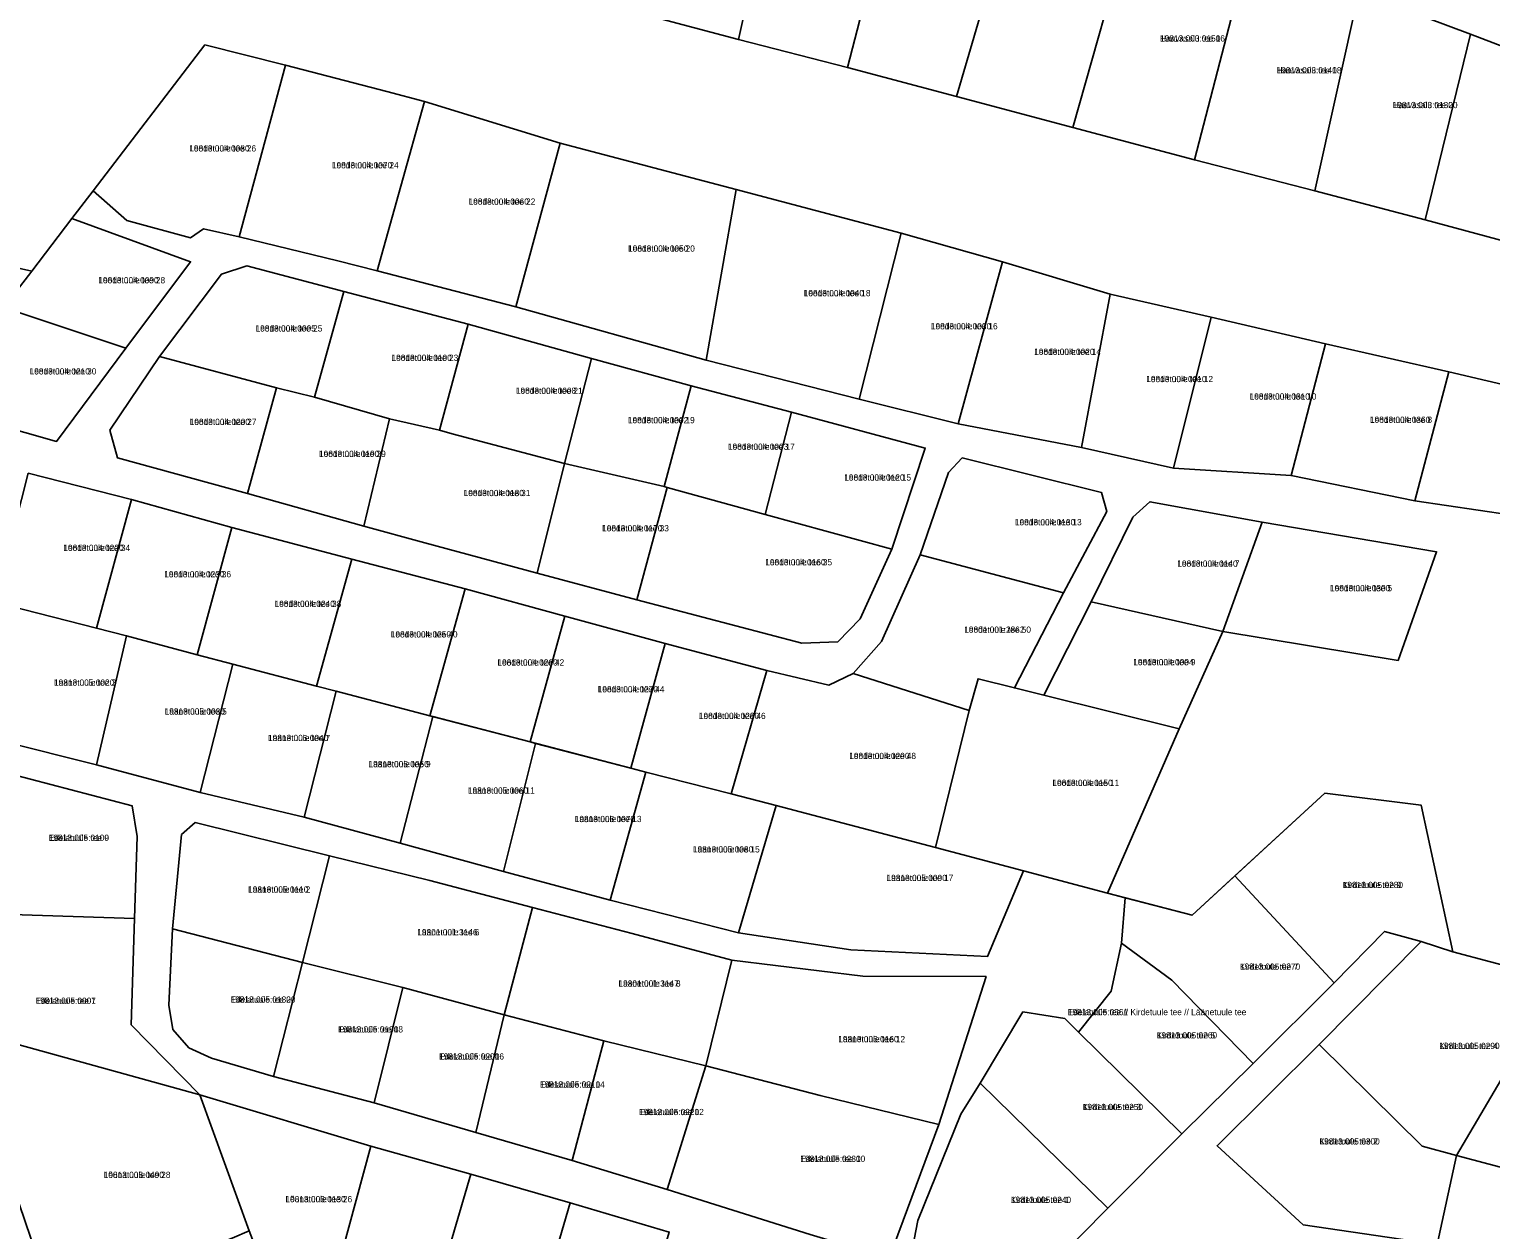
# Model space of a CAD drawing. Extents: x 516875 to 535633, y 6574491 to 6593094.
# Drawn here: x 517650.6 to 518002.1, y 6583914.7 to 6584203.6 of the extents above; entities that cross this region are included whole.
import ezdxf

# ---------------------------------------------------------------- set-up
doc = ezdxf.new("R2010")
doc.units = 0
for name, color, linetype in [('L_AADRESS', 7, 'Continuous'), ('PIIR', 7, 'Continuous'), ('TUNNUS', 7, 'Continuous')]:
    doc.layers.add(name, color=color, linetype=linetype)

msp = doc.modelspace()

# ---------------------------------------------------------------- linework, layer by layer
at = {"layer": 'PIIR'}
for points in [[(517802.26, 6584255.24), (517831.46, 6584247.67), (517821.18, 6584201.16), (517790.64, 6584209.2)], [(517831.46, 6584247.67), (517859.74, 6584242.19), (517847.33, 6584194.39), (517821.18, 6584201.16)], [(517859.74, 6584242.19), (517887.99, 6584236.68), (517873.61, 6584187.42), (517847.33, 6584194.39)], [(517887.99, 6584236.68), (517915.38, 6584228.93), (517901.53, 6584179.93), (517873.61, 6584187.42)], [(517943.51, 6584221.11), (517930.79, 6584172.17), (517901.53, 6584179.93), (517915.38, 6584228.93)], [(517943.51, 6584221.11), (517970.3, 6584212.5), (517959.76, 6584164.74), (517930.79, 6584172.17)], [(517970.3, 6584212.5), (517997.17, 6584202.41), (517986.26, 6584157.75), (517959.76, 6584164.74)], [(517997.17, 6584202.41), (518026.14, 6584191.36), (518015.68, 6584149.83), (517986.26, 6584157.75)], [(517674.1, 6584157.6), (517665.96, 6584164.7), (517692.86, 6584199.83), (517712.21, 6584194.93), (517701.1, 6584153.69), (517692.5, 6584155.6), (517689.4, 6584153.4)], [(517712.21, 6584194.93), (517736.59, 6584188.6), (517745.66, 6584186.23), (517734.23, 6584145.46), (517724.78, 6584147.89), (517701.1, 6584153.69)], [(517745.66, 6584186.23), (517778.25, 6584176.21), (517767.64, 6584136.85), (517734.23, 6584145.46)], [(517778.25, 6584176.21), (517820.61, 6584165.03), (517813.39, 6584123.96), (517767.64, 6584136.85)], [(517820.61, 6584165.03), (517860.28, 6584154.5), (517850.21, 6584114.59), (517813.39, 6584123.96)], [(517594.89, 6584064.17), (517581.91, 6584058.31), (517564.54, 6584099.9), (517607.05, 6584155.33), (517651.21, 6584145.42), (517644.46, 6584136.64), (517626.64, 6584113.1), (517620.18, 6584104.83), (517599.06, 6584076.92)], [(517660.88, 6584158.06), (517689.39, 6584147.67), (517673.82, 6584126.88), (517644.46, 6584136.64), (517651.21, 6584145.42)], [(517860.28, 6584154.5), (517884.62, 6584147.65), (517874, 6584108.63), (517850.21, 6584114.59)], [(517702.9, 6584146.7), (517696.8, 6584144.7), (517681.93, 6584124.89), (517669.95, 6584107.17), (517671.84, 6584100.48), (517703.12, 6584091.88), (517731.02, 6584084.05), (517745.73, 6584080.04), (517772.71, 6584072.69), (517796.71, 6584066.29), (517836.42, 6584055.86), (517845.01, 6584056.22), (517850.43, 6584061.73), (517858.02, 6584078.53), (517866.07, 6584102.81), (517833.94, 6584111.47), (517809.8, 6584117.8), (517785.8, 6584124.4), (517756.11, 6584132.62), (517726.29, 6584140.47)], [(517726.29, 6584140.47), (517719.23, 6584115.04), (517710.02, 6584117.33), (517681.93, 6584124.89), (517696.8, 6584144.7), (517702.9, 6584146.7)], [(517884.62, 6584147.65), (517910.52, 6584139.88), (517903.63, 6584102.98), (517874, 6584108.63)], [(517719.23, 6584115.04), (517726.29, 6584140.47), (517756.11, 6584132.62), (517749.28, 6584107.14), (517737.27, 6584109.84)], [(517910.52, 6584139.88), (517934.79, 6584134.3), (517925.77, 6584098.03), (517903.63, 6584102.98)], [(517644.46, 6584136.64), (517673.82, 6584126.88), (517657.18, 6584104.43), (517626.64, 6584113.1)], [(517934.79, 6584134.3), (517962.35, 6584127.9), (517954.04, 6584096.21), (517925.77, 6584098.03)], [(517756.11, 6584132.62), (517785.8, 6584124.4), (517779.33, 6584099.13), (517752.28, 6584106.28), (517749.28, 6584107.14)], [(517962.35, 6584127.9), (517991.96, 6584121.14), (517983.8, 6584090.13), (517954.04, 6584096.21)], [(517710.02, 6584117.33), (517703.12, 6584091.88), (517671.84, 6584100.48), (517669.95, 6584107.17), (517681.93, 6584124.89)], [(517785.8, 6584124.4), (517809.8, 6584117.8), (517803.3, 6584093.6), (517779.33, 6584099.13)], [(517991.96, 6584121.14), (518018.27, 6584114.96), (518024.6, 6584113.47), (518019.18, 6584084.93), (518014.23, 6584085.66), (517983.8, 6584090.13)], [(517710.02, 6584117.33), (517719.23, 6584115.04), (517737.27, 6584109.84), (517731.02, 6584084.05), (517703.12, 6584091.88)], [(517833.94, 6584111.47), (517827.6, 6584086.85), (517804.01, 6584093.35), (517803.3, 6584093.6), (517809.8, 6584117.8)], [(517731.02, 6584084.05), (517737.27, 6584109.84), (517749.28, 6584107.14), (517752.28, 6584106.28), (517779.33, 6584099.13), (517772.71, 6584072.69), (517745.73, 6584080.04)], [(517833.94, 6584111.47), (517866.07, 6584102.81), (517858.02, 6584078.53), (517827.6, 6584086.85)], [(517779.33, 6584099.13), (517803.3, 6584093.6), (517804.01, 6584093.35), (517796.71, 6584066.29), (517772.71, 6584072.69)], [(517871.67, 6584096.93), (517874.93, 6584100.45), (517908.46, 6584092.12), (517909.7, 6584087.6), (517899.32, 6584068.02), (517864.88, 6584077.12)], [(517650.35, 6584096.77), (517675.23, 6584090.42), (517666.8, 6584059.53), (517645.75, 6584064.86), (517642.38, 6584065.75)], [(517804.01, 6584093.35), (517827.6, 6584086.85), (517858.02, 6584078.53), (517850.43, 6584061.73), (517845.01, 6584056.22), (517836.42, 6584055.86), (517796.71, 6584066.29)], [(517675.23, 6584090.42), (517699.35, 6584083.75), (517690.98, 6584053.09), (517673.97, 6584057.62), (517666.8, 6584059.53)], [(517916, 6584086.2), (517920.1, 6584089.9), (517947.08, 6584085.04), (517937.6, 6584058.66), (517906, 6584065.85)], [(517947.08, 6584085.04), (517989.04, 6584077.89), (517979.78, 6584051.73), (517937.6, 6584058.66)], [(517699.35, 6584083.75), (517728.2, 6584076.11), (517719.66, 6584045.52), (517699.58, 6584050.82), (517690.98, 6584053.09)], [(517728.2, 6584076.11), (517755.42, 6584068.93), (517746.97, 6584038.42), (517724.37, 6584044.3), (517719.66, 6584045.52)], [(517855.58, 6584056.29), (517864.88, 6584077.12), (517899.32, 6584068.02), (517887.5, 6584045.13), (517878.76, 6584047.33), (517876.62, 6584039.66), (517848.7, 6584048.62)], [(517755.42, 6584068.93), (517779.39, 6584062.4), (517771.09, 6584032.11), (517746.97, 6584038.42)], [(517646.35, 6584044.51), (517639.15, 6584046.56), (517645.75, 6584064.86), (517666.8, 6584059.53), (517673.97, 6584057.62), (517666.74, 6584026.6), (517644.05, 6584032.34)], [(517937.6, 6584058.66), (517927.09, 6584035.31), (517894.56, 6584043.4), (517906, 6584065.85)], [(517779.39, 6584062.4), (517803.5, 6584055.8), (517795.24, 6584025.79), (517771.09, 6584032.11)], [(517690.98, 6584053.09), (517699.58, 6584050.82), (517691.68, 6584019.98), (517666.74, 6584026.6), (517673.97, 6584057.62)], [(517803.5, 6584055.8), (517828, 6584049.3), (517819.37, 6584019.64), (517798.91, 6584024.85), (517795.24, 6584025.79)], [(517719.66, 6584045.52), (517724.37, 6584044.3), (517716.68, 6584014), (517691.68, 6584019.98), (517699.58, 6584050.82)], [(517828, 6584049.3), (517842.85, 6584045.8), (517848.7, 6584048.62), (517876.62, 6584039.66), (517868.54, 6584006.7), (517830.21, 6584016.79), (517819.37, 6584019.64)], [(517876.62, 6584039.66), (517878.76, 6584047.33), (517887.5, 6584045.13), (517894.56, 6584043.4), (517927.09, 6584035.31), (517909.87, 6583995.74), (517889.7, 6584001.09), (517868.54, 6584006.7)], [(517724.37, 6584044.3), (517746.97, 6584038.42), (517747.69, 6584038.23), (517739.83, 6584007.76), (517716.68, 6584014)], [(517772.35, 6584031.78), (517764.66, 6584000.98), (517739.83, 6584007.76), (517747.69, 6584038.23), (517771.09, 6584032.11)], [(517798.91, 6584024.86), (517790.33, 6583994.05), (517764.66, 6584000.98), (517772.35, 6584031.78), (517795.24, 6584025.79)], [(517675.35, 6584016.77), (517676.59, 6584009.38), (517675.92, 6583989.6), (517631.57, 6583991.05), (517635.38, 6584018.08), (517636.16, 6584027.04)], [(517819.37, 6584019.64), (517830.21, 6584016.79), (517821.14, 6583986.2), (517790.33, 6583994.05), (517798.91, 6584024.86)], [(517940.54, 6583999.91), (517962.17, 6584019.81), (517985.32, 6584016.88), (517992.97, 6583981.64), (517985.35, 6583984.1), (517976.51, 6583986.53), (517964.39, 6583974.12)], [(517868.54, 6584006.7), (517889.7, 6584001.09), (517881.04, 6583980.51), (517848.16, 6583982.1), (517821.14, 6583986.2), (517830.21, 6584016.79)], [(517722.77, 6584004.72), (517690.53, 6584012.7), (517687.24, 6584009.84), (517685.07, 6583987.19), (517684.13, 6583968.81), (517685.13, 6583962.94), (517689.01, 6583958.54), (517694.4, 6583956), (517709.32, 6583951.59), (517733.53, 6583945.3), (517758, 6583938.17), (517781.12, 6583931.43), (517803.99, 6583924.42), (517838.37, 6583913.57), (517857.4, 6583907.94), (517869.33, 6583940.11), (517880.7, 6583975.65), (517851.04, 6583975.74), (517819.59, 6583979.63), (517795.57, 6583986.06), (517771.63, 6583992.28), (517746.94, 6583998.75)], [(517687.24, 6584009.84), (517690.53, 6584012.7), (517722.77, 6584004.72), (517716.33, 6583979.03), (517685.07, 6583987.19)], [(517740.41, 6583973), (517716.33, 6583979.03), (517722.77, 6584004.72), (517746.94, 6583998.75), (517771.63, 6583992.28), (517764.77, 6583966.45)], [(517913.22, 6583983.71), (517914.17, 6583994.61), (517930.21, 6583990.41), (517940.54, 6583999.91), (517964.39, 6583974.12), (517944.91, 6583954.71), (517925.39, 6583974.84)], [(517675.92, 6583989.6), (517675.15, 6583964.07), (517691.62, 6583947.17), (517639.15, 6583961.76), (517633.5, 6583964.01), (517628.61, 6583965.96), (517630.91, 6583986.34), (517631.57, 6583991.05)], [(517788.79, 6583960.23), (517764.77, 6583966.45), (517771.63, 6583992.28), (517795.57, 6583986.06), (517819.59, 6583979.63), (517813.27, 6583954.21)], [(517689.01, 6583958.54), (517685.13, 6583962.94), (517684.13, 6583968.81), (517685.07, 6583987.19), (517716.33, 6583979.03), (517709.32, 6583951.59), (517694.4, 6583956)], [(517910.77, 6583972.17), (517913.22, 6583983.71), (517925.39, 6583974.84), (517944.91, 6583954.71), (517927.79, 6583937.85), (517902.91, 6583962.3)], [(517960.79, 6583959.34), (517985.35, 6583984.1), (517992.97, 6583981.64), (518011.08, 6583976.77), (518018.58, 6583974.75), (517993.78, 6583932.65), (517985.59, 6583934.85)], [(517740.41, 6583973), (517733.53, 6583945.3), (517709.32, 6583951.59), (517716.33, 6583979.03)], [(517813.27, 6583954.21), (517819.59, 6583979.63), (517851.04, 6583975.74), (517880.7, 6583975.65), (517869.33, 6583940.11), (517840.79, 6583947.04)], [(517740.41, 6583973), (517764.77, 6583966.45), (517758, 6583938.17), (517733.53, 6583945.3)], [(518012.22, 6583927.69), (517993.78, 6583932.65), (518018.58, 6583974.75), (518032.77, 6583970.93), (518046.75, 6583967.18), (518032.08, 6583899), (518003.93, 6583906.25)], [(517764.77, 6583966.45), (517788.79, 6583960.23), (517781.12, 6583931.43), (517758, 6583938.17)], [(517889.55, 6583967.18), (517899.65, 6583965.54), (517902.91, 6583962.3), (517927.79, 6583937.85), (517909.96, 6583919.91), (517879.24, 6583950.04)], [(517639.15, 6583961.76), (517691.62, 6583947.17), (517703.49, 6583914.48), (517699.43, 6583912.76), (517656.57, 6583896.21), (517639.72, 6583945.75), (517633.5, 6583964.01)], [(517813.27, 6583954.21), (517803.99, 6583924.42), (517781.12, 6583931.43), (517788.79, 6583960.23)], [(517936.25, 6583934.96), (517960.79, 6583959.34), (517985.59, 6583934.85), (517993.78, 6583932.65), (517989.16, 6583911.17), (517956.97, 6583915.91)], [(517813.27, 6583954.21), (517840.79, 6583947.04), (517869.33, 6583940.11), (517857.4, 6583907.94), (517838.37, 6583913.57), (517803.99, 6583924.42)], [(517863.33, 6583903.37), (517863.38, 6583912.42), (517864.32, 6583916.96), (517874.64, 6583942.55), (517879.24, 6583950.04), (517909.96, 6583919.91), (517890.91, 6583900.6), (517883.11, 6583898.78)], [(517703.49, 6583914.48), (517691.62, 6583947.17), (517732.77, 6583934.82), (517722.39, 6583896.74), (517707.48, 6583904.06)], [(517732.77, 6583934.82), (517756.81, 6583928.1), (517745.67, 6583890.09), (517722.39, 6583896.74)], [(517756.81, 6583928.1), (517780.68, 6583921.26), (517769.63, 6583883.34), (517745.67, 6583890.09)], [(517780.68, 6583921.26), (517804.49, 6583914.18), (517793.44, 6583876.69), (517769.63, 6583883.34)]]:
    msp.add_lwpolyline(points, close=True, dxfattribs=at)
for points in [[(518018.27, 6584114.96), (517991.96, 6584121.14), (517962.35, 6584127.9), (517934.79, 6584134.3), (517910.52, 6584139.88), (517884.62, 6584147.65), (517860.28, 6584154.5), (517820.61, 6584165.03), (517778.25, 6584176.21), (517745.66, 6584186.23), (517736.59, 6584188.6), (517712.21, 6584194.93), (517692.86, 6584199.83), (517665.96, 6584164.7), (517660.88, 6584158.06), (517651.21, 6584145.42), (517607.05, 6584155.33), (517543.49, 6584169.71), (517513.07, 6584245.83)], [(517997.94, 6584210.98), (518025.49, 6584201.06), (518053.46, 6584190.76), (518106.5, 6584188), (518106.98, 6584179.93), (518078.33, 6584179.94), (518055.07, 6584180.27), (518026.14, 6584191.36), (517997.17, 6584202.41), (517970.3, 6584212.5)], [(517790.64, 6584209.2), (517821.18, 6584201.16), (517847.33, 6584194.39), (517873.61, 6584187.42), (517901.53, 6584179.93), (517930.79, 6584172.17), (517959.76, 6584164.74), (517986.26, 6584157.75), (518015.68, 6584149.83)], [(517626.64, 6584113.1), (517657.18, 6584104.43), (517673.82, 6584126.88), (517689.39, 6584147.67), (517660.88, 6584158.06), (517665.96, 6584164.7), (517674.1, 6584157.6), (517689.4, 6584153.4), (517692.5, 6584155.6), (517701.1, 6584153.69), (517724.78, 6584147.89), (517734.23, 6584145.46), (517767.64, 6584136.85), (517813.39, 6584123.96), (517850.21, 6584114.59), (517874, 6584108.63), (517903.63, 6584102.98), (517925.77, 6584098.03), (517954.04, 6584096.21), (517983.8, 6584090.13), (518014.23, 6584085.66)], [(518011.08, 6583976.77), (517992.97, 6583981.64), (517985.32, 6584016.88), (517962.17, 6584019.81), (517930.21, 6583990.41), (517909.87, 6583995.74), (517927.09, 6584035.31), (517937.6, 6584058.66), (517979.78, 6584051.73), (517989.04, 6584077.89), (517947.08, 6584085.04), (517920.1, 6584089.9), (517916, 6584086.2), (517906, 6584065.85), (517894.56, 6584043.4), (517887.5, 6584045.13), (517899.32, 6584068.02), (517909.7, 6584087.6), (517908.46, 6584092.12), (517874.93, 6584100.45), (517871.67, 6584096.93), (517864.88, 6584077.12), (517855.58, 6584056.29), (517848.7, 6584048.62), (517842.85, 6584045.8), (517828, 6584049.3), (517803.5, 6584055.8), (517779.39, 6584062.4), (517755.42, 6584068.93), (517728.2, 6584076.11), (517699.35, 6584083.75), (517675.23, 6584090.42), (517650.35, 6584096.77)], [(517644.05, 6584032.34), (517666.74, 6584026.6), (517691.68, 6584019.98), (517716.68, 6584014), (517739.83, 6584007.76), (517764.66, 6584000.98), (517790.33, 6583994.05), (517821.14, 6583986.2), (517848.16, 6583982.1), (517881.04, 6583980.51), (517889.7, 6584001.09), (517909.87, 6583995.74), (517914.17, 6583994.61), (517913.22, 6583983.71), (517910.77, 6583972.17), (517902.91, 6583962.3), (517899.65, 6583965.54), (517889.55, 6583967.18), (517879.24, 6583950.04), (517874.64, 6583942.55), (517864.32, 6583916.96), (517863.38, 6583912.42)], [(517804.49, 6583914.18), (517780.68, 6583921.26), (517756.81, 6583928.1), (517732.77, 6583934.82), (517691.62, 6583947.17), (517675.15, 6583964.07), (517675.92, 6583989.6), (517676.59, 6584009.38), (517675.35, 6584016.77), (517636.16, 6584027.04)], [(517890.91, 6583900.6), (517909.96, 6583919.91), (517927.79, 6583937.85), (517944.91, 6583954.71), (517964.39, 6583974.12), (517976.51, 6583986.53), (517985.35, 6583984.1), (517960.79, 6583959.34), (517936.25, 6583934.96), (517956.97, 6583915.91), (517989.16, 6583911.17), (517993.78, 6583932.65), (518012.22, 6583927.69)]]:
    msp.add_lwpolyline(points, dxfattribs=at)

# ---------------------------------------------------------------- texts
at = {"layer": 'L_AADRESS'}
for s, p in [('Haavasalu tee 16', (517922.52, 6584200.65)), ('Haavasalu tee 18', (517950.54, 6584192.98)), ('Haavasalu tee 20', (517978.46, 6584184.62)), ('Loodetuule tee 26', (517689.09, 6584174.19)), ('Loodetuule tee 24', (517723.38, 6584170.13)), ('Loodetuule tee 22', (517756.24, 6584161.38)), ('Loodetuule tee 20', (517794.6, 6584150.09)), ('Loodetuule tee 28', (517667.22, 6584142.47)), ('Loodetuule tee 18', (517836.84, 6584139.36)), ('Loodetuule tee 25', (517705.02, 6584130.87)), ('Loodetuule tee 16', (517867.41, 6584131.39)), ('Loodetuule tee 14', (517892.26, 6584125.25)), ('Loodetuule tee 23', (517737.71, 6584123.8)), ('Loodetuule tee 30', (517650.69, 6584120.54)), ('Loodetuule tee 12', (517919.21, 6584118.69)), ('Loodetuule tee 21', (517767.62, 6584115.88)), ('Loodetuule tee 10', (517944.06, 6584114.5)), ('Loodetuule tee 27', (517689.18, 6584108.38)), ('Loodetuule tee 19', (517794.56, 6584108.8)), ('Loodetuule tee 8', (517973, 6584108.9)), ('Loodetuule tee 29', (517720.28, 6584100.69)), ('Loodetuule tee 17', (517818.62, 6584102.41)), ('Loodetuule tee 15', (517846.59, 6584095)), ('Loodetuule tee 31', (517755.06, 6584091.27)), ('Loodetuule tee 13', (517887.62, 6584084.24)), ('Loodetuule tee 33', (517788.36, 6584082.78)), ('Loodetuule tee 34', (517658.8, 6584078.08)), ('Loodetuule tee 35', (517827.6, 6584074.61)), ('Loodetuule tee 7', (517926.68, 6584074.28)), ('Loodetuule tee 36', (517683.07, 6584071.72)), ('Loodetuule tee 5', (517963.39, 6584068.38)), ('Loodetuule tee 38', (517709.59, 6584064.61)), ('Loodetuule tee 50', (517875.43, 6584058.39)), ('Loodetuule tee 40', (517737.54, 6584057.26)), ('Loodetuule tee 42', (517763.18, 6584050.5)), ('Loodetuule tee 9', (517916.09, 6584050.58)), ('Läänetuule tee 3', (517656.56, 6584045.65)), ('Loodetuule tee 44', (517787.3, 6584044.05)), ('Läänetuule tee 5', (517683.16, 6584038.71)), ('Loodetuule tee 46', (517811.62, 6584037.63)), ('Läänetuule tee 7', (517708.02, 6584032.33)), ('Loodetuule tee 48', (517847.78, 6584028)), ('Läänetuule tee 9', (517732.18, 6584026.04)), ('Läänetuule tee 11', (517756.09, 6584019.68)), ('Loodetuule tee 11', (517896.64, 6584021.53)), ('Läänetuule tee 13', (517781.78, 6584012.83)), ('Edelatuule tee 9', (517655.28, 6584008.32)), ('Läänetuule tee 15', (517810.2, 6584005.53)), ('Läänetuule tee 17', (517856.75, 6583998.65)), ('Läänetuule tee 2', (517703.23, 6583995.87)), ('Kirdetuule tee 9', (517966.45, 6583996.96)), ('Läänetuule tee 6', (517743.91, 6583985.58)), ('Kirdetuule tee 7', (517941.72, 6583977.31)), ('Läänetuule tee 8', (517792.29, 6583973.25)), ('Edelatuule tee 7', (517652.13, 6583969.11)), ('Edelatuule tee 20', (517699.01, 6583969.39)), ('Edelatuule tee // Kirdetuule tee // Läänetuule tee', (517900.34, 6583966.37)), ('Edelatuule tee 18', (517724.86, 6583962.22)), ('Kirdetuule tee 5', (517921.74, 6583960.78)), ('Läänetuule tee 12', (517845.16, 6583959.87)), ('Kirdetuule tee 4', (517989.68, 6583958.23)), ('Edelatuule tee 16', (517749.15, 6583955.7)), ('Edelatuule tee 14', (517773.39, 6583948.95)), ('Edelatuule tee 12', (517797.2, 6583942.33)), ('Kirdetuule tee 3', (517903.93, 6583943.54)), ('Kirdetuule tee 2', (517960.86, 6583935.26)), ('Edelatuule tee 10', (517836.02, 6583931.08)), ('Lõunatuule tee 28', (517668.5, 6583927.21)), ('Lõunatuule tee 26', (517712.2, 6583921.37)), ('Kirdetuule tee 1', (517886.64, 6583921.19))]:
    msp.add_text(s, height=1.5, dxfattribs=at).set_placement(p)
at = {"layer": 'TUNNUS'}
for s, p in [('19813:003:0150', (517922.52, 6584200.65)), ('19813:003:0140', (517950.54, 6584192.98)), ('19813:003:0130', (517978.46, 6584184.62)), ('19813:004:0080', (517689.09, 6584174.19)), ('19813:004:0070', (517723.38, 6584170.13)), ('19813:004:0060', (517756.24, 6584161.38)), ('19813:004:0050', (517794.6, 6584150.09)), ('19813:004:0090', (517667.22, 6584142.47)), ('19813:004:0040', (517836.84, 6584139.36)), ('19813:004:0005', (517705.02, 6584130.87)), ('19813:004:0030', (517867.41, 6584131.39)), ('19813:004:0020', (517892.26, 6584125.25)), ('19813:004:0100', (517737.71, 6584123.8)), ('19813:004:0210', (517650.69, 6584120.54)), ('19813:004:0010', (517919.21, 6584118.69)), ('19813:004:0008', (517767.62, 6584115.88)), ('19813:004:0310', (517944.06, 6584114.5)), ('19813:004:0200', (517689.18, 6584108.38)), ('19813:004:0002', (517794.56, 6584108.8)), ('19813:004:0360', (517973, 6584108.9)), ('19813:004:0190', (517720.28, 6584100.69)), ('19813:004:0003', (517818.62, 6584102.41)), ('19813:004:0120', (517846.59, 6584095)), ('19813:004:0180', (517755.06, 6584091.27)), ('19813:004:0130', (517887.62, 6584084.24)), ('19813:004:0170', (517788.36, 6584082.78)), ('19813:004:0220', (517658.8, 6584078.08)), ('19813:004:0160', (517827.6, 6584074.61)), ('19813:004:0140', (517926.68, 6584074.28)), ('19813:004:0230', (517683.07, 6584071.72)), ('19813:004:0300', (517963.39, 6584068.38)), ('19813:004:0240', (517709.59, 6584064.61)), ('19801:001:2862', (517875.43, 6584058.39)), ('19813:004:0250', (517737.54, 6584057.26)), ('19813:004:0260', (517763.18, 6584050.5)), ('19813:004:0004', (517916.09, 6584050.58)), ('19813:005:0020', (517656.56, 6584045.65)), ('19813:004:0270', (517787.3, 6584044.05)), ('19813:005:0030', (517683.16, 6584038.71)), ('19813:004:0280', (517811.62, 6584037.63)), ('19813:005:0040', (517708.02, 6584032.33)), ('19813:004:0290', (517847.78, 6584028)), ('19813:005:0050', (517732.18, 6584026.04)), ('19813:004:0150', (517896.64, 6584021.53)), ('19813:005:0060', (517756.09, 6584019.68)), ('19813:005:0070', (517781.78, 6584012.83)), ('19813:005:0100', (517655.28, 6584008.32)), ('19813:005:0080', (517810.2, 6584005.53)), ('19813:005:0090', (517856.75, 6583998.65)), ('19813:005:0110', (517703.23, 6583995.87)), ('19813:005:0280', (517966.45, 6583996.96)), ('19801:001:3146', (517743.91, 6583985.58)), ('19813:005:0270', (517941.72, 6583977.31)), ('19801:001:3147', (517792.29, 6583973.25)), ('19813:005:0001', (517652.13, 6583969.11)), ('19813:005:0180', (517699.01, 6583969.39)), ('19813:005:0361', (517900.34, 6583966.37)), ('19813:005:0190', (517724.86, 6583962.22)), ('19813:005:0260', (517921.74, 6583960.78)), ('19813:005:0160', (517845.16, 6583959.87)), ('19813:005:0290', (517989.68, 6583958.23)), ('19813:005:0200', (517749.15, 6583955.7)), ('19813:005:0210', (517773.39, 6583948.95)), ('19813:005:0250', (517903.93, 6583943.54)), ('19813:005:0220', (517797.2, 6583942.33)), ('19813:005:0300', (517960.86, 6583935.26)), ('19813:005:0230', (517836.02, 6583931.08)), ('19813:006:0490', (517668.5, 6583927.21)), ('19813:006:0130', (517712.2, 6583921.37)), ('19813:005:0240', (517886.64, 6583921.19))]:
    msp.add_text(s, height=1.5, dxfattribs=at).set_placement(p)

doc.saveas('drawing.dxf')
